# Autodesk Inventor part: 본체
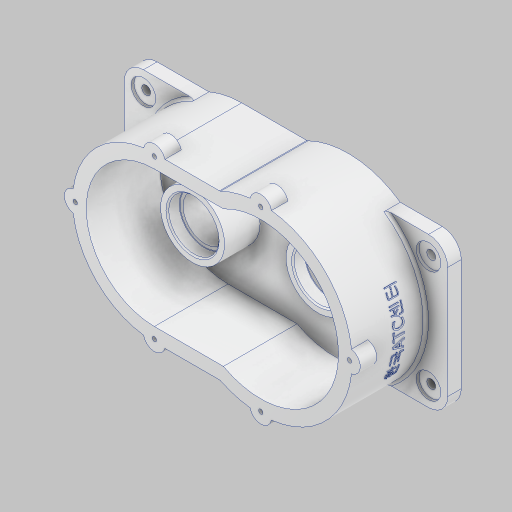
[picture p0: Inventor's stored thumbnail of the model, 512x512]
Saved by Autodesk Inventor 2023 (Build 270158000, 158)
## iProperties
Created: 2025-09
Part Number: 본체
Material: 알루미늄 6061
Document SubType Name: Modeling
Designer: home
Density: 2.7 g/cm^3
Appearance: 알루미늄 - 평지
Mass: 1574.89 g
Surface Area: 1312.34 cm^2
Volume: 583.292 cm^3
Author: home
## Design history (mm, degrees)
sketch "스케치1"
  geometry: L1 (118.5, -55)-(-118.5, -55); L2 (-118.5, -55)-(-118.5, 55); L3 (-118.5, 55)-(118.5, 55); L4 (118.5, 55)-(118.5, -55); L5 (118.5, -55)-(-118.5, 55); L6 (-118.5, -55)-(118.5, 55); 1 further point
  constraints: 12 end point, 2 midpoint, 2 parallel, 1 horizontal, 1 perpendicular
  dimensions: "d0" = 237 distance of L2.end L3.end; "d1" = 110 distance of L1.end L2.end
extrude "돌출1" new body sketch "스케치1" distance "d2" = 10; taper "d3" = 0 deg
fillet "모깎기1" dims "d4" = 14
sketch "스케치2"
  geometry: L1 (-118.5, 41)-(-118.5, -41) reference; L2 (118.5, -41)-(118.5, 41) reference; L3 (104.5, 55)-(-104.5, 55) reference; L4 (-104.5, -55)-(104.5, -55) reference; L5 (-42.5, 66.391)-(-42.5, -77.11); L6 (-118.5, 0)-(118.5, 0); L7 (35.5, 66.391)-(35.5, -81.26); L8 (-42.5, -50)-(8.132, -50); L9 (-42.5, 50)-(8.132, 50); L10 (-42.5, -60)-(5.684, -60); L11 (5.684, 60)-(-42.5, 60); A1 r 50 centre (-42.5, 0) between (-42.5, 50) and (-42.5, -50); A2 r 57 centre (35.5, 0) between (8.132, -50) and (8.132, 50); A3 r 67 centre (35.5, 0) between (5.684, -60) and (5.684, 60); A4 r 60 centre (-42.5, 0) between (-42.5, 60) and (-42.5, -60); 1 further point
  constraints: 14 end point, 8 point on circle, 5 point on line, 4 centre point, 2 midpoint, 2 parallel, 2 tangent, 2 vertical, 1 perpendicular, 3 other
  dimensions: "d5" = 76 distance from line of A1.centre L1; "d6" = 78 distance of A2.centre A1.centre; "d9" = 55 distance from line of L4 A2.centre (derived); "d10" = 57 radius of A2; "d11" = 50 radius of A1; "d12" = 10 radial gap between concentric circles of A1 A4
extrude "돌출2" join sketch "스케치2" distance "d13" = 64; taper "d14" = 0 deg
sketch "스케치3"
  geometry: L1 (-118.5, 41)-(-118.5, -41) reference; L2 (118.5, -41)-(118.5, 41) reference; L3 (-118.5, 0)-(118.5, 0); L4 (-118.5, 58)-(118.5, 58); L5 (-42.5, 0)-(-42.5, -84.517); L6 (-42.5, -60)-(5.684, -60) reference; L7 (-118.5, -58)-(-57.862, -58); L8 (-50.5, -58)-(-34.5, -58); L9 (35.5, 0)-(35.5, -79.976); L10 (27.5, -65)-(43.5, -65); L11 (-50.5, 58)-(-34.5, 58); L12 (27.5, 65)-(43.5, 65); L13 (-100.5, 0)-(-100.5, -84.517); L14 (-100.5, 8)-(-100.5, -8); L15 (0, 0)-(0, -78.559); L16 (100.5, 0)-(100.5, -84.517); L17 (100.5, 8)-(100.5, -8); A1 r 50 centre (-42.5, 0) between (-42.5, 50) and (-42.5, -50) reference; A2 r 57 centre (35.5, 0) between (8.132, -50) and (8.132, 50) reference; A3 r 8 centre (-42.5, -58) between (-50.5, -58) and (-34.5, -58); A4 r 60 centre (-42.5, 0) between (-42.5, 60) and (-42.5, -60) reference; A5 r 57 centre (35.5, 0) between (50.467, -55) and (50.467, 55) reference; A6 r 8 centre (35.5, -65) between (27.5, -65) and (43.5, -65); A7 r 8 centre (-42.5, 58) between (-34.5, 58) and (-50.5, 58); A8 r 8 centre (35.5, 65) between (43.5, 65) and (27.5, 65); A9 r 8 centre (-100.5, 0) between (-100.5, 8) and (-100.5, -8); A10 r 8 centre (100.5, 0) between (100.5, -8) and (100.5, 8); 6 further points
  constraints: 28 end point, 13 point on circle, 11 symmetric about line, 8 midpoint, 6 centre point, 5 parallel, 3 vertical, 2 coincident, 2 point on line, 1 horizontal alignment, 3 other
  dimensions: "d16" = 58 distance between parallel lines of L3 L4; "d17" = 16 diameter of A3; "d21" = 16 diameter of A6; "d22" = 58 distance between parallel lines of L3 L8; "d23" = 65 distance between parallel lines of L3 L10; "d24" = 58 distance between parallel lines of L5 L13; "d25" = 16 diameter of A9; "d26" = 58 distance between parallel lines of L5 L14
extrude "돌출3" join sketch "스케치3" distance "d18" = 12; taper "d19" = 0 deg
sketch "스케치4"
  geometry: L1 (-42.5, 50)-(8.132, 50) reference; L2 (8.132, -50)-(-42.5, -50) reference; C1 r 23.5 at (-42.5, 0); A1 r 50 centre (-42.5, 0) between (-42.5, 50) and (-42.5, -50) reference; A2 r 57 centre (35.5, 0) between (8.132, -50) and (8.132, 50) reference; 1 further point
  constraints: 1 centre point, 1 coincident
  dimensions: "d27" = 47 diameter of C1
extrude "돌출4" join sketch "스케치4" distance "d29" = 26; taper "d30" = 0 deg
sketch "스케치5"
  geometry: C1 r 23.5 at (35.5, 0); A1 r 57 centre (35.5, 0) between (8.132, -50) and (8.132, 50) reference; 1 further point
  constraints: 1 centre point, 1 coincident
  dimensions: "d31" = 47 diameter of C1
extrude "돌출5" join sketch "스케치5" distance "d32" = 12; taper "d33" = 0 deg
sketch "스케치9"
  geometry: L1 (42.5, 10)-(42.5, 10) reference; L2 (42.5, 10)-(42.5, 64) reference; L3 (42.5, 64)-(42.5, 64) reference; L4 (42.5, 10)-(42.5, 64) reference; L5 (66, 36)-(19, 36) reference; L6 (66, 10)-(66, 36) reference; L7 (19, 10)-(19, 36) reference; L8 (-12, 10)-(-12, 22) reference; L9 (-12, 22)-(-59, 22) reference; L10 (-59, 10)-(-59, 22) reference; L11 (42.5, 42.623)-(42.5, -26.9); L12 (61, 36)-(61, 27); L13 (56.5, 11)-(56.5, 8); L14 (56.5, 8)-(42.5, 8); L15 (61, 27)-(58.5, 27); L16 (58.5, 27)-(58.5, 11); L17 (56.5, 11)-(58.5, 11); L18 (61, 36)-(42.5, 36); 5 further points
  constraints: 16 end point, 5 point on line, 3 midpoint, 2 horizontal, 2 perpendicular, 1 vertical
  dimensions: "d42" = 37 diameter of L12 L11; "d44" = 28 diameter of L13 L11; "d45" = 32 diameter of L16 L11; "d46" = 9 distance from line of point (59.75, 27) L5; "d47" = 16 distance of L15.end L16.end; "d48" = 3 distance from line of L14 point (57.5, 11)
revolve "회전1" sketch "스케치9" stored, may be unused: angle "d49" = 360 deg
sketch "스케치10"
  geometry: L1 (-12, 10)-(-12, 22) reference; L2 (-59, 10)-(-59, 22) reference; L3 (-35.5, 22)-(-35.5, -8.141); L4 (-12, 22)-(-59, 22) reference; L5 (-17, 22)-(-17, 13); L6 (-17, 13)-(-20.5, 13); L7 (-20.5, 13)-(-20.5, 8.3); L8 (-20.5, 8.3)-(-18, 8.3); L9 (-5.684, 0)-(-73.762, 0) reference; L10 (-18, 8.3)-(-18, 0); L11 (-18, 0)-(-35.5, 0); L12 (-50.467, 0)-(-20.533, 0) reference; L13 (-17, 22)-(-35.5, 22); 2 further points
  constraints: 16 end point, 4 perpendicular, 2 midpoint, 2 point on line, 2 vertical, 1 collinear
  dimensions: "d51" = 37 diameter of L5 L3; "d52" = 35 diameter of L10 L3; "d53" = 30 diameter of L7 L3; "d54" = 9 distance between parallel lines of L4 L6; "d55" = 8.3 distance between parallel lines of L9 L8
revolve "회전2" sketch "스케치10" stored, may be unused: angle "d56" = 360 deg
fillet "모깎기2" dims "d57" = 0.3
chamfer "모따기1" distance "d58" = 1; stored, may be unused: second distance "d59" = 2, angle "d60" = 45 deg
fillet "모깎기3" dims "d64" = 0.3
fillet "모깎기4" dims "d65" = 0.3
sketch "스케치11"
  geometry: A1 r 67 centre (35.5, 0) between (102.038, 7.851) and (43.351, 66.538) reference; A2 r 8 centre (35.5, 65) between (43.351, 66.538) and (27.649, 66.538) reference; A3 r 8 centre (-42.5, 58) between (-34.754, 60) and (-50.361, 59.483) reference; A4 r 8 centre (-100.5, 0) between (-101.983, 7.861) and (-101.983, -7.861) reference; A5 r 8 centre (-42.5, -58) between (-50.361, -59.483) and (-34.754, -60) reference; A6 r 8 centre (35.5, -65) between (27.649, -66.538) and (43.351, -66.538) reference; A7 r 8 centre (100.5, 0) between (102.038, -7.851) and (102.038, 7.851) reference; 7 further points
  constraints: 6 coincident
hole "구멍2" sketch "스케치11" at (-42.5, 58), (35.5, 65), (100.5, 0), (35.5, -65), (-42.5, -58), (-100.5, 0) diameter "d66" = 3.242; stored, may be unused: countersink angle "d70" = 90 deg, drill point angle "d72" = 118 deg; dims "d67" = 8, "d68" = 4, "d69" = 2, "d71" = 10
sketch "스케치12"
  geometry: L1 (-66.479, 55)-(-104.5, 55) reference; L2 (-118.5, 41)-(-118.5, -41) reference; L3 (-104.5, -55)-(-66.479, -55) reference; L4 (73.762, -55)-(104.5, -55) reference; L5 (118.5, -41)-(118.5, 41) reference; L6 (104.5, 55)-(73.762, 55) reference; A1 r 14 centre (-104.5, 41) between (-104.5, 55) and (-118.5, 41) reference; A2 r 14 centre (-104.5, -41) between (-118.5, -41) and (-104.5, -55) reference; A3 r 14 centre (104.5, -41) between (104.5, -55) and (118.5, -41) reference; A4 r 14 centre (104.5, 41) between (118.5, 41) and (104.5, 55) reference; 1 further point
chamfer "모따기3" distance "d73" = 1; stored, may be unused: second distance "d74" = 2, angle "d75" = 45 deg
chamfer "모따기4" distance "d76" = 0.8; stored, may be unused: second distance "d77" = 2, angle "d78" = 60 deg
hole "구멍3" sketch "스케치12" diameter "d79" = 6.6; stored, may be unused: countersink angle "d83" = 90 deg, drill point angle "d85" = 0 deg; dims "d80" = 6, "d81" = 18, "d82" = 2, "d84" = 10
sketch "스케치13"
  geometry: L1 (-18.637, -58.923)-(-53.607, -58.923); L2 (-53.607, -58.923)-(-53.607, -49.327); L3 (-53.607, -49.327)-(-18.637, -49.327); L4 (-18.637, -49.327)-(-18.637, -58.923); 2 further points
  constraints: 8 end point, 2 parallel, 1 horizontal, 1 midpoint, 1 perpendicular
  dimensions: "d86" = 49.3274 distance from line of point (0, 0) L3; "d87" = 9.59534 distance between parallel lines of L3 L1; "d88" = 34.96967 distance between parallel lines of L2 L4; "d89" = 18.6369 horizontal distance of point (0, 0) point (-18.637, -54.125)
extrude "돌출6" join sketch "스케치13" distance "d90" = 10; taper "d91" = 0 deg
node "작업 평면1"
sketch "스케치14"
  geometry: L1 (-29.534, 0)-(29.534, 0); L2 (29.534, 0)-(29.534, 60); L3 (29.534, 60)-(-29.534, 60); L4 (-29.534, 60)-(-29.534, 0); L5 (-41, 0)-(41, 0) reference; 3 further points
  constraints: 3 midpoint, 2 other
  dimensions: "d92" = 30 distance from line of L5 point (-29.534, 30)
feature "엠보싱1" sketch "스케치14" dims "d0" = 237, "d1" = 110, "d93" = 0.5, "d94" = 0
fillet "모깎기5" dims "d95" = 2
fillet "모깎기6" dims "d96" = 2
node "솔리드1"
mirror "미러1"
node "투영된 루프1"
feature "A9D066F2-1C7D-4E18-AEED-F7BC21143FA4" dims "d79" = 6.6, "d80" = 6, "d81" = 18, "d82" = 2, "d83" = 90 deg, "d84" = 10, "d85" = 0
other parameters: "d8" = 114, "d15" = 58, "d20" = 65
